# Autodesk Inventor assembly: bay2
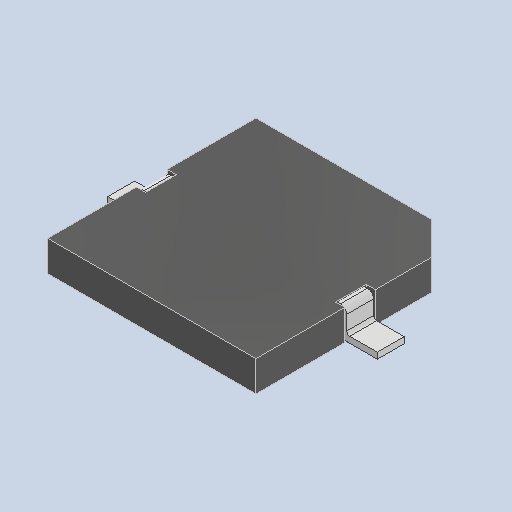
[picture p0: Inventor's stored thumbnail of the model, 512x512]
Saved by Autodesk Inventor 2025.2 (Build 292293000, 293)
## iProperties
Created: 2025-04
Part Number: bay2
Description: PART--DESC
Document SubType Name: Assembly
Designer: BennF
Author: BennF
Revision Number: NONE
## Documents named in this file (3)
- C:\Users\BennF\Nextcloud\Benutzer\CNC JarBeRi\existing parts\Electronics\RepRap A4988 Shied (USE WITHOUT ARDUINO)\reprap-a4988-1.snapshot.1\RepRap\RepRap\bay2_1.iam
- C:\Users\BennF\Nextcloud\Benutzer\CNC JarBeRi\existing parts\Electronics\RepRap A4988 Shied (USE WITHOUT ARDUINO)\reprap-a4988-1.snapshot.1\RepRap\RepRap\bay2 Geometry.ipt
- C:\Users\BennF\Nextcloud\Benutzer\CNC JarBeRi\existing parts\Electronics\RepRap A4988 Shied (USE WITHOUT ARDUINO)\reprap-a4988-1.snapshot.1\RepRap\RepRap\pin15.ipt
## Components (2 placed, 2 different names)
1. bay2 Geometry
2. pin15
